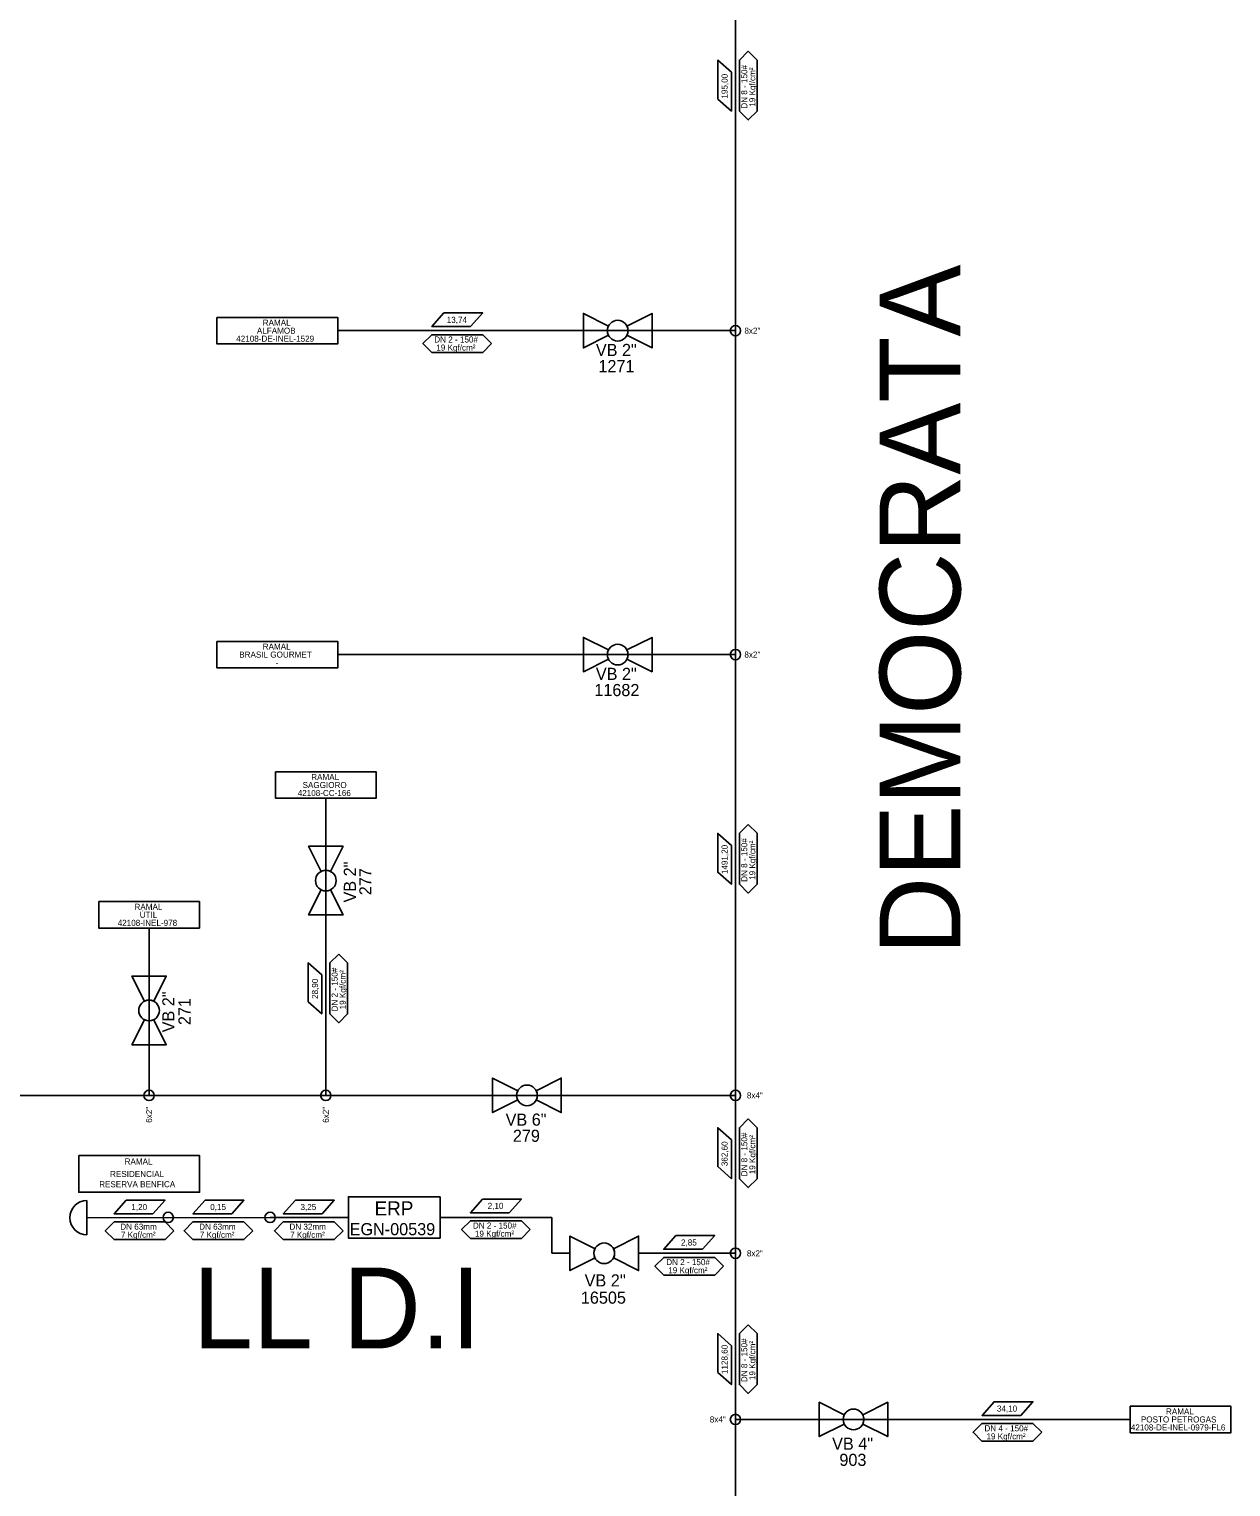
# Model space of a CAD drawing. Extents: x 656692 to 673945, y 7585994 to 7599066.
# Drawn here: x 671700 to 672295, y 7596885 to 7597607 of the extents above; entities that cross this region are included whole.
import ezdxf

# ---------------------------------------------------------------- set-up
doc = ezdxf.new("R2010")
doc.units = 0
for name, color, linetype in [('SIMBOLO', 7, 'Continuous'), ('TEXTO', 7, 'Continuous'), ('TUBO_ACO_GN_2', 7, 'Continuous'), ('TUBO_ACO_GN_4', 7, 'Continuous'), ('TUBO_ACO_GN_6', 7, 'Continuous'), ('TUBO_ACO_GN_8', 7, 'Continuous'), ('TUBO_PEAD_GN_32', 7, 'Continuous'), ('TUBO_PEAD_GN_63', 7, 'Continuous'), ('VALVULA_ACO_2', 7, 'Continuous'), ('VALVULA_ACO_4', 7, 'Continuous'), ('VALVULA_ACO_6', 7, 'Continuous')]:
    doc.layers.add(name, color=color, linetype=linetype)

# ---------------------------------------------------------------- blocks, each defined once
blk = doc.blocks.new('INTERLIGACAO_5')
at = {"layer": 'SIMBOLO'}
blk.add_circle((0, 0), 1.28, dxfattribs=at)
for start, end in [(0, 180), (180, 0)]:
    blk.add_arc((0, 0), 1.28, start, end, dxfattribs=at)
blk = doc.blocks.new('VALVULA_DN_1')
at = {"layer": 'VALVULA_ACO_4'}
for points in [[(-1.14, 0.57), (-4.25, 2.13), (-4.25, -2.13), (-1.14, -0.57)], [(-1.14, -0.57), (-4.25, -2.13), (-4.25, 2.13), (-1.14, 0.57)], [(1.14, -0.57), (4.25, -2.13), (4.25, 2.13), (1.14, 0.57)], [(1.14, -0.57), (4.25, -2.13), (4.25, 2.13), (1.14, 0.57)]]:
    blk.add_lwpolyline(points, dxfattribs=at)
blk.add_circle((0, 0), 1.28, dxfattribs=at)
for start, end in [(90, 270), (153.4349, 206.5651), (270, 90), (0, 26.5651), (333.4349, 0)]:
    blk.add_arc((0, 0), 1.28, start, end, dxfattribs=at)
blk = doc.blocks.new('VALVULA_DN_3')
at = {"layer": 'VALVULA_ACO_6'}
for points in [[(-1.14, 0.57), (-4.25, 2.13), (-4.25, -2.13), (-1.14, -0.57)], [(-1.14, -0.57), (-4.25, -2.13), (-4.25, 2.13), (-1.14, 0.57)], [(1.14, -0.57), (4.25, -2.13), (4.25, 2.13), (1.14, 0.57)], [(1.14, -0.57), (4.25, -2.13), (4.25, 2.13), (1.14, 0.57)]]:
    blk.add_lwpolyline(points, dxfattribs=at)
blk.add_circle((0, 0), 1.28, dxfattribs=at)
for start, end in [(90, 270), (153.4349, 206.5651), (270, 90), (0, 26.5651), (333.4349, 0)]:
    blk.add_arc((0, 0), 1.28, start, end, dxfattribs=at)
blk = doc.blocks.new('VALVULA_ACO_3')
at = {"layer": 'VALVULA_ACO_2'}
for points in [[(-1.14, 0.57), (-4.25, 2.13), (-4.25, -2.13), (-1.14, -0.57)], [(-1.14, -0.57), (-4.25, -2.13), (-4.25, 2.13), (-1.14, 0.57)], [(1.14, -0.57), (4.25, -2.13), (4.25, 2.13), (1.14, 0.57)], [(1.14, -0.57), (4.25, -2.13), (4.25, 2.13), (1.14, 0.57)]]:
    blk.add_lwpolyline(points, dxfattribs=at)
blk.add_circle((0, 0), 1.28, dxfattribs=at)
for start, end in [(90, 270), (153.4349, 206.5651), (270, 90), (0, 26.5651), (333.4349, 0)]:
    blk.add_arc((0, 0), 1.28, start, end, dxfattribs=at)

msp = doc.modelspace()

# ---------------------------------------------------------------- linework, layer by layer
at = {"layer": 'SIMBOLO'}
for points in [[(672055.95, 7597596.08), (672060.33, 7597591.71), (672060.33, 7597566.45), (672055.95, 7597562.08), (672051.58, 7597566.45), (672051.58, 7597591.71), (672055.95, 7597596.08)], [(671928.83, 7597451.41), (671924.46, 7597447.04), (671899.21, 7597447.04), (671894.83, 7597451.41), (671899.21, 7597455.79), (671924.46, 7597455.79), (671928.83, 7597451.41)], [(672055.95, 7597213.34), (672060.33, 7597208.97), (672060.33, 7597183.72), (672055.95, 7597179.34), (672051.58, 7597183.72), (672051.58, 7597208.97), (672055.95, 7597213.34)], [(671853.07, 7597149.22), (671857.45, 7597144.84), (671857.45, 7597119.59), (671853.07, 7597115.22), (671848.7, 7597119.59), (671848.7, 7597144.84), (671853.07, 7597149.22)], [(672055.95, 7597067.59), (672060.33, 7597063.21), (672060.33, 7597037.96), (672055.95, 7597033.59), (672051.58, 7597037.96), (672051.58, 7597063.21), (672055.95, 7597067.59)], [(671771.46, 7597012.22), (671767.09, 7597007.85), (671741.84, 7597007.85), (671737.46, 7597012.22), (671741.84, 7597016.6), (671767.09, 7597016.6), (671771.46, 7597012.22)], [(671810.52, 7597012.22), (671806.14, 7597007.85), (671780.89, 7597007.85), (671776.52, 7597012.22), (671780.89, 7597016.6), (671806.14, 7597016.6), (671810.52, 7597012.22)], [(671855.25, 7597012.22), (671850.87, 7597007.85), (671825.62, 7597007.85), (671821.25, 7597012.22), (671825.62, 7597016.6), (671850.87, 7597016.6), (671855.25, 7597012.22)], [(671947.95, 7597012.79), (671943.57, 7597008.41), (671918.32, 7597008.41), (671913.95, 7597012.79), (671918.32, 7597017.16), (671943.57, 7597017.16), (671947.95, 7597012.79)], [(672043.71, 7596994.67), (672039.34, 7596990.3), (672014.09, 7596990.3), (672009.71, 7596994.67), (672014.09, 7596999.05), (672039.34, 7596999.05), (672043.71, 7596994.67)], [(672055.95, 7596965.7), (672060.33, 7596961.32), (672060.33, 7596936.07), (672055.95, 7596931.7), (672051.58, 7596936.07), (672051.58, 7596961.32), (672055.95, 7596965.7)], [(672201.32, 7596912.44), (672196.95, 7596908.06), (672171.7, 7596908.06), (672167.32, 7596912.44), (672171.7, 7596916.81), (672196.95, 7596916.81), (672201.32, 7596912.44)]]:
    msp.add_lwpolyline(points, dxfattribs=at)
for points in [[(672047.58, 7597585.69), (672047.58, 7597566.47), (672040.83, 7597572.47), (672040.83, 7597591.69)], [(671792.75, 7597464.35), (671852.58, 7597464.35), (671852.58, 7597451.23), (671792.75, 7597451.23)], [(671918.44, 7597459.79), (671899.22, 7597459.79), (671905.22, 7597466.54), (671924.44, 7597466.54)], [(671792.75, 7597304), (671852.58, 7597304), (671852.58, 7597290.87), (671792.75, 7597290.87)], [(671821.79, 7597239.44), (671871.61, 7597239.44), (671871.61, 7597226.32), (671821.79, 7597226.32)], [(672047.58, 7597202.95), (672047.58, 7597183.73), (672040.83, 7597189.73), (672040.83, 7597208.95)], [(671734.26, 7597175.17), (671784.09, 7597175.17), (671784.09, 7597162.04), (671734.26, 7597162.04)], [(671844.7, 7597138.83), (671844.7, 7597119.61), (671837.95, 7597125.61), (671837.95, 7597144.83)], [(672047.58, 7597057.2), (672047.58, 7597037.98), (672040.83, 7597043.98), (672040.83, 7597063.2)], [(671724.35, 7597049.45), (671784.17, 7597049.45), (671784.17, 7597031.24), (671724.35, 7597031.24)], [(671761.07, 7597020.6), (671741.85, 7597020.6), (671747.85, 7597027.35), (671767.07, 7597027.35)], [(671800.13, 7597020.6), (671780.91, 7597020.6), (671786.91, 7597027.35), (671806.13, 7597027.35)], [(671844.86, 7597020.6), (671825.64, 7597020.6), (671831.64, 7597027.35), (671850.86, 7597027.35)], [(671903.3, 7597029.02), (671857.92, 7597029.02), (671857.92, 7597008.6), (671903.29, 7597008.59)], [(671937.56, 7597021.16), (671918.34, 7597021.16), (671924.34, 7597027.91), (671943.56, 7597027.91)], [(672033.32, 7597003.05), (672014.1, 7597003.05), (672020.1, 7597009.8), (672039.32, 7597009.8)], [(672047.58, 7596955.31), (672047.58, 7596936.09), (672040.83, 7596942.09), (672040.83, 7596961.31)], [(672190.93, 7596920.81), (672171.71, 7596920.81), (672177.71, 7596927.56), (672196.93, 7596927.56)], [(672245.13, 7596925.38), (672294.96, 7596925.38), (672294.96, 7596912.25), (672245.13, 7596912.25)]]:
    msp.add_lwpolyline(points, close=True, dxfattribs=at)
at = {"layer": 'TUBO_ACO_GN_2'}
for p, q in [((671852.58, 7597457.79), (672049.58, 7597457.79)), ((671852.58, 7597297.44), (672049.58, 7597297.44)), ((671846.7, 7597079.24), (671846.7, 7597226.32)), ((671759.17, 7597079.24), (671759.17, 7597162.04)), ((671958.57, 7597018.8), (671903.29, 7597018.8)), ((671958.57, 7597001.05), (671958.57, 7597018.8)), ((671967.58, 7597001.05), (671958.57, 7597001.05)), ((672001.6, 7597001.05), (672049.58, 7597001.05))]:
    msp.add_line(p, q, dxfattribs=at)
at = {"layer": 'TUBO_ACO_GN_4'}
msp.add_line((672049.58, 7596918.81), (672245.13, 7596918.81), dxfattribs=at)
at = {"layer": 'TUBO_ACO_GN_6'}
msp.add_line((671196.65, 7597079.24), (672049.58, 7597079.24), dxfattribs=at)
at = {"layer": 'TUBO_ACO_GN_8'}
for q in [(672049.58, 7597695.03), (672049.58, 7596215.28)]:
    msp.add_line((672049.58, 7597079.24), q, dxfattribs=at)
at = {"layer": 'TUBO_PEAD_GN_32'}
msp.add_line((671857.92, 7597018.81), (671819.08, 7597018.81), dxfattribs=at)
at = {"layer": 'TUBO_PEAD_GN_63'}
for p, q in [((671728.38, 7597027.19), (671728.38, 7597010.18)), ((671819.08, 7597018.81), (671728.38, 7597018.68))]:
    msp.add_line(p, q, dxfattribs=at)
msp.add_arc((671728.38, 7597018.68), 8.51, 90, 270, dxfattribs=at)

# ---------------------------------------------------------------- block references
at = {"layer": 'SIMBOLO', "xscale": 2, "yscale": 2}
for p in [(672049.58, 7597457.79), (672049.58, 7597297.44), (672049.58, 7597079.24), (672049.58, 7597001.05), (672049.58, 7596918.81)]:
    msp.add_blockref('INTERLIGACAO_5', p, dxfattribs=at)
at = {"layer": 'SIMBOLO', "xscale": 2, "yscale": 2, "rotation": 90}
for p in [(671759.17, 7597079.24), (671846.7, 7597079.24), (671768.64, 7597018.82), (671819.07, 7597018.82)]:
    msp.add_blockref('INTERLIGACAO_5', p, dxfattribs=at)
at = {"layer": 'VALVULA_ACO_2', "xscale": 4, "yscale": 4}
for p in [(671991.28, 7597457.79), (671991.28, 7597297.44), (671984.59, 7597001.05)]:
    msp.add_blockref('VALVULA_ACO_3', p, dxfattribs=at)
at = {"layer": 'VALVULA_ACO_2', "xscale": 4, "yscale": 4, "rotation": 90}
for p in [(671846.7, 7597185.55), (671759.17, 7597121.27)]:
    msp.add_blockref('VALVULA_ACO_3', p, dxfattribs=at)
at = {"layer": 'VALVULA_ACO_4', "xscale": 4, "yscale": 4}
msp.add_blockref('VALVULA_DN_1', (672108.06, 7596918.81), dxfattribs=at)
at = {"layer": 'VALVULA_ACO_6', "xscale": 4, "yscale": 4}
msp.add_blockref('VALVULA_DN_3', (671946.34, 7597079.24), dxfattribs=at)

# ---------------------------------------------------------------- texts
for s, height, rotation, p in [('8x2"', 3, 0, (672054.03, 7597456.29)), ('VB 2"', 6, 0, (671980.46, 7597445.24)), ('1271', 6, 0, (671981.71, 7597437.24)), ('8x2"', 3, 0, (672054.03, 7597295.94)), ('VB 2"', 6, 0, (671980.46, 7597284.89)), ('11682', 6, 0, (671979.69, 7597276.89)), ('VB 2"', 6, 90, (671861.62, 7597174.72)), ('277', 6, 90, (671869.29, 7597178.31)), ('VB 2"', 6, 90, (671771.72, 7597110.44)), ('271', 6, 90, (671779.72, 7597114.03)), (' 8x4"', 3, 0, (672054.15, 7597077.74)), ('6x2"', 3, 90, (671760.67, 7597065.66)), ('6x2"', 3, 90, (671848.2, 7597065.66)), ('8x4"', 3, 0, (672036.9, 7596917.31))]:
    msp.add_text(s, height=height, rotation=rotation).set_placement(p)
for s, p in [('VB 6"', (671935.76, 7597064.24)), ('279', (671939.35, 7597056.24)), ('EGN-00539', (671858.52, 7597010.02)), ("VB 2''", (671974.91, 7596984.63)), ('16505', (671973.03, 7596976.11)), ('VB 4"', (672097.48, 7596903.81)), ('903', (672101.07, 7596895.81))]:
    msp.add_text(s, height=6).set_placement(p)
at = {"layer": 'SIMBOLO'}
msp.add_text(' 8x2"', height=3, rotation=0, dxfattribs=at).set_placement((672054.15, 7596999.55))
at = {"layer": 'TEXTO'}
for s, height, rotation, p in [('DN 8 - 150#', 3, 90, (672055.44, 7597567.68)), ('19 Kgf/cm²', 3, 90, (672059.45, 7597568.68)), ('195,00', 3, 90, (672045.7, 7597572.67)), ('DEMOCRATA', 40, 90, (672161.01, 7597148.78)), ('1491,20', 3, 90, (672045.7, 7597188.77)), ('DN 8 - 150#', 3, 90, (672055.44, 7597184.94)), ('19 Kgf/cm²', 3, 90, (672059.45, 7597185.94)), ('DN 2 - 150#', 3, 90, (671852.56, 7597120.81)), ('19 Kgf/cm²', 3, 90, (671856.57, 7597121.82)), ('28,90', 3, 90, (671842.82, 7597126.97)), ('DN 8 - 150#', 3, 90, (672055.44, 7597039.19)), ('19 Kgf/cm²', 3, 90, (672059.45, 7597040.19)), ('362,60', 3, 90, (672045.7, 7597044.18)), ('ERP', 7, 359.99261, (671870.84, 7597019.81)), ('DN 8 - 150#', 3, 90, (672055.44, 7596937.29)), ('19 Kgf/cm²', 3, 90, (672059.45, 7596938.3)), ('1128,60', 3, 90, (672045.7, 7596941.28))]:
    msp.add_text(s, height=height, rotation=rotation, dxfattribs=at).set_placement(p)
for s, height, p in [('RAMAL', 3, (671815.45, 7597460.25)), ('13,74', 3, (671906.59, 7597461.66)), ('42108-DE-INEL-1529', 3, (671802.35, 7597452.33)), ('ALFAMOB', 3, (671812.57, 7597456.29)), ('DN 2 - 150#', 3, (671900.43, 7597451.93)), ('19 Kgf/cm²', 3, (671901.43, 7597447.92)), ('BRASIL GOURMET', 3, (671803.83, 7597295.94)), ('RAMAL', 3, (671815.45, 7597299.9)), ('-', 3, (671821.8, 7597291.97)), ('SAGGIORO', 3, (671835.2, 7597231.38)), ('RAMAL', 3, (671839.48, 7597235.34)), ('42108-CC-166', 3, (671832.79, 7597227.42)), ('RAMAL', 3, (671751.95, 7597171.06)), ('ÚTIL', 3, (671754.55, 7597167.1)), ('42108-INEL-978', 3, (671743.63, 7597163.14)), ('RAMAL', 3, (671747.04, 7597045.01)), ('RESERVA BENFICA', 3, (671734.45, 7597033.77)), ('RESIDENCIAL', 3, (671739.85, 7597038.83)), ('1,20', 3, (671750.39, 7597022.47)), ('0,15', 3, (671789.44, 7597022.47)), ('3,25', 3, (671834.17, 7597022.47)), ('2,10', 3, (671926.87, 7597023.04)), ('DN 63mm', 3, (671744.92, 7597012.74)), ('DN 63mm', 3, (671783.98, 7597012.74)), ('DN 32mm', 3, (671828.71, 7597012.74)), ('DN 2 - 150#', 3, (671919.54, 7597013.3)), ('7 Kgf/cm²', 3, (671745.23, 7597008.72)), ('7 Kgf/cm²', 3, (671784.28, 7597008.72)), ('7 Kgf/cm²', 3, (671829.01, 7597008.72)), ('19 Kgf/cm²', 3, (671920.55, 7597009.29)), ('2,85', 3, (672022.64, 7597004.92)), ('LL D.I', 40, (671780.81, 7596954.01)), ('DN 2 - 150#', 3, (672015.31, 7596995.19)), ('19 Kgf/cm²', 3, (672016.31, 7596991.18)), ('34,10', 3, (672179.08, 7596922.69)), ('RAMAL', 3, (672262.83, 7596921.27)), ('DN 4 - 150#', 3, (672172.92, 7596912.95)), ('42108-DE-INEL-0979-FL6', 3, (672245.42, 7596913.35)), ('POSTO PETROGAS', 3, (672250.4, 7596917.31)), ('19 Kgf/cm²', 3, (672173.92, 7596908.94))]:
    msp.add_text(s, height=height, dxfattribs=at).set_placement(p)

doc.saveas('drawing.dxf')
